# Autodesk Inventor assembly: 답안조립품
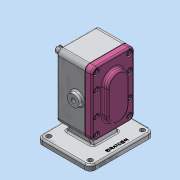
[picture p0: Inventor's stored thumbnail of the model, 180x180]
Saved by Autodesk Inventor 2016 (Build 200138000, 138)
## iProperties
Created: 2020-04
Part Number: 답안조립품
Document SubType Name: Assembly
Designer: MIRAE
Author: MIRAE
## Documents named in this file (11)
- C:\Users\MIRAE\Desktop\700407V1003\답안조립품.iam
- C:\Users\MIRAE\Desktop\700407V1003\본체.ipt
- C:\Users\MIRAE\Desktop\700407V1003\스퍼기어.ipt
- C:\Users\MIRAE\Desktop\700407V1003\서브축.ipt
- C:\Users\MIRAE\Desktop\700407V1003\메인축.ipt
- C:\Users\MIRAE\Desktop\700407V1003\키 6 x 6 x 18.ipt
- C:\Users\MIRAE\Desktop\700407V1003\베어링부시.ipt
- C:\Users\MIRAE\Desktop\700407V1003\커버.ipt
- C:\Users\MIRAE\Desktop\700407V1003\개스킷.ipt
- C:\Users\MIRAE\Desktop\700407V1003\오일 실 16 28 7.ipt
- C:\Users\MIRAE\Desktop\700407V1003\볼트 M5.ipt
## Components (1 placed, 1 different names)
1. 개스킷:1
